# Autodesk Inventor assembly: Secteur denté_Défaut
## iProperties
Shininess: 64.0
Length Units: 11269
Angle Units: 11279
Time Units: 11290
Mass Units: 11283
Length Display Precision: 3
Angle Display Precision: 2
Compacted: True
Created: 2006-01
Part Number: Secteur denté_Défaut
Document SubType Name: Assembly
Designer: Fricot
Density: 0.0
Volumn: 0.0
Area: 0.0
PropertySet Name: Model Information
Control State: 0
Master: False
Checked Out: False
Author: Fricot
